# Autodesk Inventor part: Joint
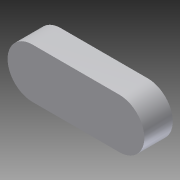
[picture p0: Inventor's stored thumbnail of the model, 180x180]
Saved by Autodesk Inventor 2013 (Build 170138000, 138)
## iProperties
Created: 2004-11
Document SubType Name: Modeling
Designer: Autodesk, Inc.
Manufacturer: Standard
Standards Organization: Custom
Description: SWING ARM, JOINT
Mass: 127.24 g
Surface Area: 175.174 cm^2
Volume: 127.24 cm^3
Density: 1 g/cm^3
Material: Allgemein
CAGE: 1LJX3
Dept. ID: Product Design
Description #2: ---
Finish #1: ---
Finish #2: ---
Material ID: ---
Project Number: ---
Author: Autodesk, Inc.
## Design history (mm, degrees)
sketch "Sketch1"
  geometry: L1 (-38.894, 22.225)-(38.894, 22.225); L2 (38.894, 22.225)-(38.894, -22.225); L3 (38.894, -22.225)-(-38.894, -22.225); L4 (-38.894, -22.225)-(-38.894, 22.225); C1 r 22.225 at (-38.894, 0); 3 further points
  constraints: 8 end point, 3 midpoint, 2 parallel, 2 vertical alignment, 1 centre point, 1 horizontal, 1 horizontal alignment, 1 perpendicular, 1 tangent, 2 other
  dimensions: "d0" = 44.45 distance of L1.end L2.end; "d1" = 77.7875 distance of L1.start L1.end
extrude "Extrusion1" new body sketch "Sketch1" stored distance "d2" = 25.4; taper "d3" = 0 deg
body "Solid1"
